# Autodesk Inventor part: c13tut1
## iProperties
Shininess: 64.0
Length Units: 11269
Angle Units: 11279
Time Units: 11290
Mass Units: 11283
Length Display Precision: 3
Angle Display Precision: 2
Compacted: True
Created: 2002-04
Part Number: c13tut1
Document SubType Name: Modeling
Density: 0.0
Volumn: 0.0
Area: 0.0
PropertySet Name: Model Information
Control State: 0
Master: False
Checked Out: False
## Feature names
1. Extrusion1
2. Fillet2
